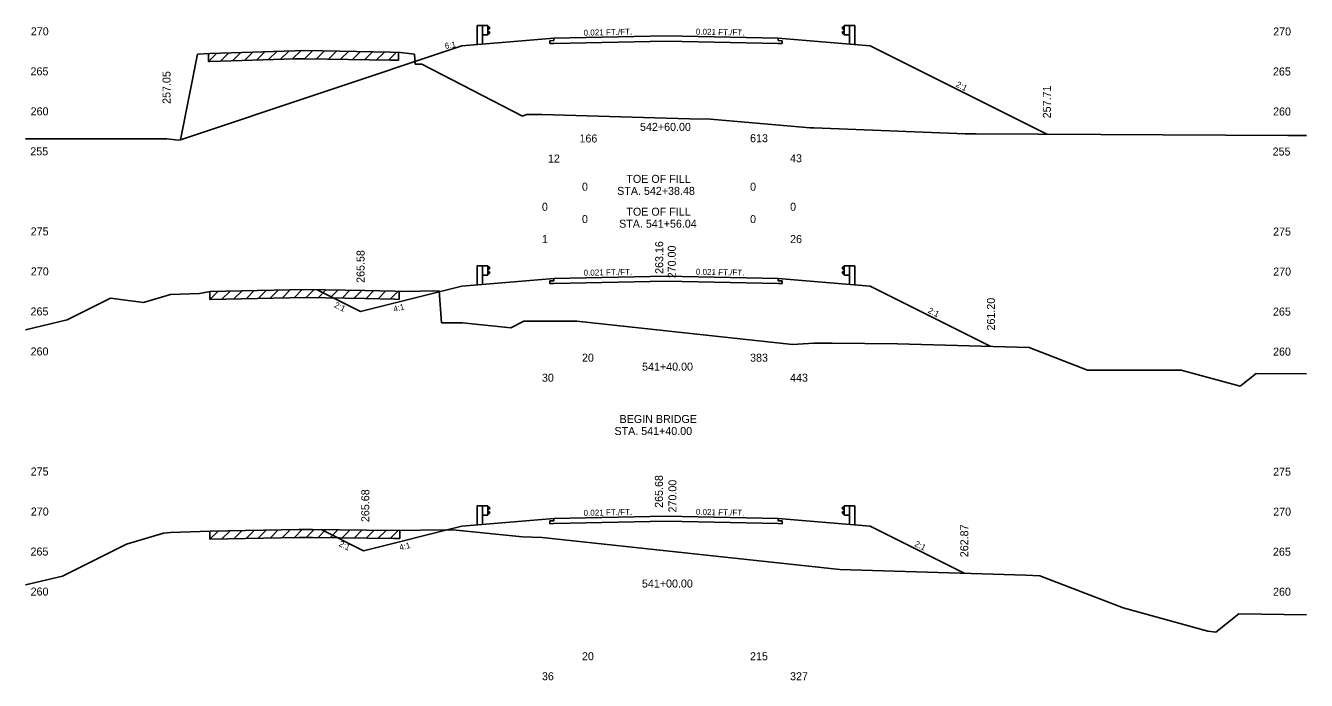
# Model space of a CAD drawing. Extents: x 2967 to 4323, y -3677 to -817.
# Drawn here: x 3555.3 to 3715.3, y -2295.4 to -2213.5 of the extents above; entities that cross this region are included whole.
import ezdxf

# ---------------------------------------------------------------- set-up
doc = ezdxf.new("R2010")
doc.units = 0
for name, color, linetype in [('Level 1', 7, 'Continuous'), ('Level 10', 7, 'Continuous'), ('Level 11', 7, 'Continuous'), ('Level 12', 7, 'Continuous'), ('Level 24', 7, 'Continuous'), ('Level 3', 7, 'Continuous'), ('Level 32', 7, 'Continuous'), ('Level 33', 7, 'Continuous'), ('Level 59', 7, 'Continuous'), ('Level 6', 7, 'Continuous'), ('Level 60', 7, 'Continuous'), ('Level 61', 7, 'Continuous'), ('Level 7', 7, 'Continuous')]:
    doc.layers.add(name, color=color, linetype=linetype)

msp = doc.modelspace()

# ---------------------------------------------------------------- linework, layer by layer
at = {"layer": 'Level 11'}
for p, q in [((3621.35, -2215.43), (3620.85, -2215.44)), ((3620.85, -2215.44), (3620.85, -2215.78)), ((3620.85, -2215.78), (3621.35, -2215.77)), ((3621.35, -2215.13), (3621.35, -2215.43)), ((3649.35, -2215.43), (3649.35, -2215.13)), ((3649.85, -2215.44), (3649.35, -2215.43)), ((3649.35, -2215.77), (3649.85, -2215.78)), ((3649.85, -2215.78), (3649.85, -2215.44)), ((3621.35, -2245.43), (3620.85, -2245.44)), ((3620.85, -2245.44), (3620.85, -2245.78)), ((3620.85, -2245.78), (3621.35, -2245.77)), ((3621.35, -2245.13), (3621.35, -2245.43)), ((3649.35, -2245.43), (3649.35, -2245.13)), ((3649.85, -2245.44), (3649.35, -2245.43)), ((3649.35, -2245.77), (3649.85, -2245.78)), ((3649.85, -2245.78), (3649.85, -2245.44)), ((3621.35, -2275.13), (3621.35, -2275.43)), ((3649.35, -2275.43), (3649.35, -2275.13)), ((3621.35, -2275.43), (3620.85, -2275.44)), ((3620.85, -2275.44), (3620.85, -2275.78)), ((3620.85, -2275.78), (3621.35, -2275.77)), ((3649.85, -2275.44), (3649.35, -2275.43)), ((3649.35, -2275.77), (3649.85, -2275.78)), ((3649.85, -2275.78), (3649.85, -2275.44))]:
    msp.add_line(p, q, dxfattribs=at)
at = {"layer": 'Level 12'}
for p, q in [((3635.35, -2215.48), (3621.35, -2215.77)), ((3649.35, -2215.77), (3635.35, -2215.48)), ((3635.35, -2245.48), (3621.35, -2245.77)), ((3649.35, -2245.77), (3635.35, -2245.48)), ((3635.35, -2275.48), (3621.35, -2275.77)), ((3649.35, -2275.77), (3635.35, -2275.48))]:
    msp.add_line(p, q, dxfattribs=at)
at = {"layer": 'Level 24'}
for p, q in [((3612.41, -2213.55), (3611.75, -2213.55)), ((3611.75, -2213.55), (3611.75, -2215.93)), ((3613.08, -2213.55), (3612.41, -2213.55)), ((3612.41, -2213.55), (3612.41, -2215.88)), ((3613.08, -2214.72), (3613.08, -2213.55)), ((3613.08, -2213.62), (3613.35, -2213.82)), ((3613.35, -2213.87), (3613.08, -2214.07)), ((3613.35, -2214.39), (3613.08, -2214.19)), ((3613.35, -2213.82), (3613.35, -2213.87)), ((3613.35, -2214.44), (3613.35, -2214.39)), ((3657.62, -2213.62), (3657.35, -2213.82)), ((3657.35, -2213.82), (3657.35, -2213.87)), ((3657.35, -2213.87), (3657.62, -2214.07)), ((3657.35, -2214.39), (3657.62, -2214.19)), ((3657.35, -2214.44), (3657.35, -2214.39)), ((3657.62, -2214.72), (3657.62, -2213.55)), ((3657.62, -2213.55), (3658.28, -2213.55)), ((3658.28, -2213.55), (3658.28, -2215.88)), ((3658.28, -2213.55), (3658.95, -2213.55)), ((3658.95, -2213.55), (3658.95, -2215.93)), ((3613.08, -2214.72), (3612.41, -2214.72)), ((3613.08, -2214.64), (3613.35, -2214.44)), ((3657.62, -2214.64), (3657.35, -2214.44)), ((3657.62, -2214.72), (3658.29, -2214.72)), ((3612.41, -2243.55), (3611.75, -2243.55)), ((3611.75, -2243.55), (3611.75, -2245.93)), ((3613.08, -2243.55), (3612.41, -2243.55)), ((3612.41, -2243.55), (3612.41, -2245.88)), ((3613.08, -2244.72), (3612.41, -2244.72)), ((3613.08, -2244.72), (3613.08, -2243.55)), ((3613.08, -2243.62), (3613.35, -2243.82)), ((3613.35, -2243.87), (3613.08, -2244.07)), ((3613.35, -2244.39), (3613.08, -2244.19)), ((3613.08, -2244.64), (3613.35, -2244.44)), ((3613.35, -2243.82), (3613.35, -2243.87)), ((3613.35, -2244.44), (3613.35, -2244.39)), ((3657.62, -2243.62), (3657.35, -2243.82)), ((3657.35, -2243.82), (3657.35, -2243.87)), ((3657.35, -2243.87), (3657.62, -2244.07)), ((3657.35, -2244.39), (3657.62, -2244.19)), ((3657.35, -2244.44), (3657.35, -2244.39)), ((3657.62, -2244.64), (3657.35, -2244.44)), ((3657.62, -2244.72), (3657.62, -2243.55)), ((3657.62, -2243.55), (3658.28, -2243.55)), ((3657.62, -2244.72), (3658.29, -2244.72)), ((3658.28, -2243.55), (3658.28, -2245.88)), ((3658.28, -2243.55), (3658.95, -2243.55)), ((3658.95, -2243.55), (3658.95, -2245.93)), ((3612.41, -2273.55), (3611.75, -2273.55)), ((3611.75, -2273.55), (3611.75, -2275.93)), ((3613.08, -2273.55), (3612.41, -2273.55)), ((3612.41, -2273.55), (3612.41, -2275.88)), ((3613.08, -2274.72), (3613.08, -2273.55)), ((3657.62, -2274.72), (3657.62, -2273.55)), ((3657.62, -2273.55), (3658.28, -2273.55)), ((3658.28, -2273.55), (3658.28, -2275.88)), ((3658.28, -2273.55), (3658.95, -2273.55)), ((3658.95, -2273.55), (3658.95, -2275.93)), ((3613.08, -2274.72), (3612.41, -2274.72)), ((3613.08, -2273.62), (3613.35, -2273.82)), ((3613.35, -2273.87), (3613.08, -2274.07)), ((3613.35, -2274.39), (3613.08, -2274.19)), ((3613.08, -2274.64), (3613.35, -2274.44)), ((3613.35, -2273.82), (3613.35, -2273.87)), ((3613.35, -2274.44), (3613.35, -2274.39)), ((3657.62, -2273.62), (3657.35, -2273.82)), ((3657.35, -2273.82), (3657.35, -2273.87)), ((3657.35, -2273.87), (3657.62, -2274.07)), ((3657.35, -2274.39), (3657.62, -2274.19)), ((3657.35, -2274.44), (3657.35, -2274.39)), ((3657.62, -2274.64), (3657.35, -2274.44)), ((3657.62, -2274.72), (3658.29, -2274.72))]:
    msp.add_line(p, q, dxfattribs=at)
at = {"layer": 'Level 59'}
for p, q in [((3621.35, -2215.13), (3635.35, -2214.84)), ((3635.35, -2214.84), (3649.35, -2215.13)), ((3621.35, -2245.13), (3635.35, -2244.84)), ((3635.35, -2244.84), (3649.35, -2245.13)), ((3621.35, -2275.13), (3635.35, -2274.84)), ((3635.35, -2274.84), (3649.35, -2275.13))]:
    msp.add_line(p, q, dxfattribs=at)
at = {"layer": 'Level 6'}
for p, q in [((3609.85, -2216.09), (3621.35, -2215.13)), ((3649.35, -2215.13), (3657.35, -2215.8)), ((3657.35, -2215.8), (3660.85, -2216.09)), ((3613.35, -2245.8), (3621.35, -2245.13)), ((3649.35, -2245.13), (3657.35, -2245.8)), ((3657.35, -2245.8), (3660.85, -2246.09)), ((3609.85, -2276.09), (3621.35, -2275.13)), ((3649.35, -2275.13), (3657.35, -2275.8)), ((3657.35, -2275.8), (3660.85, -2276.09))]:
    msp.add_line(p, q, dxfattribs=at)
at = {"layer": 'Level 60'}
for p, q in [((3574.68, -2227.8), (3576.84, -2217.13)), ((3576.84, -2217.13), (3578.36, -2217.02)), ((3578.36, -2217.02), (3589, -2216.7)), ((3589, -2216.7), (3590.34, -2216.68)), ((3590.34, -2216.68), (3600.95, -2216.86)), ((3600.95, -2216.86), (3602.18, -2216.89)), ((3602.18, -2216.89), (3603.92, -2217.11)), ((3603.92, -2217.11), (3604.03, -2218.38)), ((3604.03, -2218.38), (3604.86, -2218.38)), ((3604.86, -2218.38), (3617.44, -2224.87)), ((3617.44, -2224.87), (3617.91, -2224.64)), ((3617.91, -2224.64), (3619.85, -2224.64)), ((3619.85, -2224.64), (3635.35, -2225.12)), ((3635.35, -2225.12), (3639.75, -2225.25)), ((3639.75, -2225.25), (3640.39, -2225.21)), ((3640.39, -2225.21), (3653.34, -2226.32)), ((3653.34, -2226.32), (3653.82, -2226.32)), ((3653.82, -2226.32), (3672.73, -2227.07)), ((3672.73, -2227.07), (3674.08, -2227.09)), ((3674.08, -2227.09), (3713.02, -2227.3)), ((3555.35, -2227.69), (3572.97, -2227.69)), ((3572.97, -2227.69), (3574.43, -2227.88)), ((3574.43, -2227.88), (3574.68, -2227.8)), ((3713.02, -2227.3), (3713.78, -2227.3)), ((3713.78, -2227.3), (3715.35, -2227.28)), ((3560.55, -2250.33), (3565.95, -2247.62)), ((3565.95, -2247.62), (3570.09, -2248.13)), ((3570.09, -2248.13), (3573.45, -2247.15)), ((3573.45, -2247.15), (3577.05, -2247.03)), ((3577.05, -2247.03), (3578.4, -2246.75)), ((3578.4, -2246.75), (3582.33, -2246.68)), ((3582.33, -2246.68), (3590.37, -2246.53)), ((3590.37, -2246.53), (3597.71, -2246.64)), ((3597.71, -2246.64), (3601.46, -2246.72)), ((3601.46, -2246.72), (3602.2, -2246.77)), ((3602.2, -2246.77), (3606.99, -2246.7)), ((3606.99, -2246.7), (3607.32, -2250.7)), ((3555.35, -2251.57), (3560.55, -2250.33)), ((3607.32, -2250.7), (3609.94, -2250.7)), ((3609.94, -2250.7), (3615.95, -2251.3)), ((3615.95, -2251.3), (3617.58, -2250.48)), ((3617.58, -2250.48), (3624.21, -2250.48)), ((3624.21, -2250.48), (3635.35, -2251.69)), ((3635.35, -2251.69), (3651.17, -2253.4)), ((3651.17, -2253.4), (3653.81, -2253.24)), ((3653.81, -2253.24), (3656.11, -2253.23)), ((3656.11, -2253.23), (3664.25, -2253.29)), ((3664.25, -2253.29), (3680.72, -2253.78)), ((3680.72, -2253.78), (3687.99, -2256.58)), ((3687.99, -2256.58), (3699.72, -2256.61)), ((3699.72, -2256.61), (3707.07, -2258.6)), ((3707.07, -2258.6), (3709.06, -2257.01)), ((3709.06, -2257.01), (3715.35, -2257.07)), ((3573.44, -2276.88), (3578.4, -2276.72)), ((3578.4, -2276.72), (3589.49, -2276.52)), ((3589.49, -2276.52), (3590.36, -2276.5)), ((3590.36, -2276.5), (3591.19, -2276.5)), ((3591.19, -2276.5), (3601.33, -2276.64)), ((3601.33, -2276.64), (3607.95, -2276.55)), ((3607.95, -2276.55), (3609.13, -2276.57)), ((3609.13, -2276.57), (3617.42, -2277.41)), ((3567.35, -2278.64), (3567.95, -2278.34)), ((3567.95, -2278.34), (3572.58, -2276.98)), ((3572.58, -2276.98), (3572.99, -2276.91)), ((3572.99, -2276.91), (3573.44, -2276.88)), ((3617.42, -2277.41), (3619.86, -2277.49)), ((3619.86, -2277.49), (3635.35, -2279.16)), ((3559.95, -2282.34), (3567.35, -2278.64)), ((3635.35, -2279.16), (3657.08, -2281.51)), ((3657.08, -2281.51), (3680.28, -2282.2)), ((3555.35, -2283.42), (3559.95, -2282.34)), ((3680.28, -2282.2), (3682.03, -2282.29)), ((3682.03, -2282.29), (3692.46, -2286.3)), ((3692.46, -2286.3), (3703.02, -2289.21)), ((3704.03, -2289.34), (3706.89, -2287.06)), ((3706.89, -2287.06), (3715.35, -2287.16)), ((3703.02, -2289.21), (3704.03, -2289.34))]:
    msp.add_line(p, q, dxfattribs=at)
at = {"layer": 'Level 61'}
for p, q in [((3579.23, -2217), (3578.19, -2218.04)), ((3578.19, -2217.04), (3578.19, -2218.04)), ((3580.72, -2216.95), (3579.69, -2217.98)), ((3582.22, -2216.91), (3581.19, -2217.94)), ((3583.72, -2216.86), (3582.69, -2217.89)), ((3585.22, -2216.82), (3584.19, -2217.85)), ((3586.72, -2216.77), (3585.69, -2217.8)), ((3588.22, -2216.73), (3587.19, -2217.76)), ((3589.71, -2216.69), (3588.69, -2217.71)), ((3591.18, -2216.7), (3590.19, -2217.68)), ((3592.68, -2216.72), (3591.69, -2217.7)), ((3594.18, -2216.75), (3593.19, -2217.73)), ((3595.68, -2216.77), (3594.69, -2217.76)), ((3597.18, -2216.8), (3596.19, -2217.78)), ((3598.68, -2216.82), (3597.69, -2217.81)), ((3600.18, -2216.85), (3599.19, -2217.83)), ((3601.67, -2216.88), (3600.69, -2217.86)), ((3601.92, -2217.88), (3601.92, -2216.88)), ((3578.19, -2218.04), (3578.36, -2218.02)), ((3578.36, -2218.02), (3589, -2217.7)), ((3589, -2217.7), (3590.34, -2217.68)), ((3590.34, -2217.68), (3600.95, -2217.86)), ((3600.95, -2217.86), (3601.92, -2217.88)), ((3579.4, -2246.73), (3578.38, -2247.75)), ((3578.38, -2246.75), (3578.38, -2247.75)), ((3578.38, -2247.75), (3578.4, -2247.75)), ((3578.4, -2247.75), (3582.33, -2247.68)), ((3580.89, -2246.71), (3579.88, -2247.72)), ((3582.39, -2246.68), (3581.38, -2247.7)), ((3582.33, -2247.68), (3590.37, -2247.53)), ((3583.89, -2246.65), (3582.88, -2247.67)), ((3585.39, -2246.63), (3584.38, -2247.64)), ((3586.9, -2246.6), (3585.88, -2247.62)), ((3588.4, -2246.57), (3587.38, -2247.59)), ((3589.9, -2246.54), (3588.88, -2247.56)), ((3590.37, -2247.53), (3597.71, -2247.64)), ((3591.36, -2246.55), (3590.38, -2247.53)), ((3592.86, -2246.57), (3591.88, -2247.56)), ((3594.36, -2246.59), (3593.38, -2247.58)), ((3595.86, -2246.61), (3594.88, -2247.6)), ((3597.36, -2246.63), (3596.38, -2247.62)), ((3597.71, -2247.64), (3601.46, -2247.72)), ((3598.85, -2246.66), (3597.88, -2247.64)), ((3600.35, -2246.7), (3599.38, -2247.67)), ((3601.84, -2246.75), (3600.88, -2247.71)), ((3601.46, -2247.72), (3602.02, -2247.76)), ((3602.02, -2247.76), (3602.02, -2246.76)), ((3579.4, -2276.7), (3578.38, -2277.72)), ((3578.38, -2276.72), (3578.38, -2277.72)), ((3580.9, -2276.67), (3579.88, -2277.69)), ((3582.4, -2276.65), (3581.38, -2277.66)), ((3583.9, -2276.62), (3582.88, -2277.64)), ((3585.4, -2276.59), (3584.38, -2277.61)), ((3586.9, -2276.56), (3585.88, -2277.58)), ((3588.4, -2276.54), (3587.38, -2277.55)), ((3589.9, -2276.51), (3588.88, -2277.53)), ((3591.38, -2276.5), (3590.38, -2277.5)), ((3592.87, -2276.52), (3591.88, -2277.51)), ((3594.37, -2276.55), (3593.38, -2277.53)), ((3595.87, -2276.57), (3594.88, -2277.55)), ((3597.37, -2276.59), (3596.38, -2277.57)), ((3598.87, -2276.61), (3597.88, -2277.59)), ((3600.37, -2276.63), (3599.38, -2277.61)), ((3601.89, -2276.63), (3600.88, -2277.63)), ((3602.08, -2277.63), (3602.08, -2276.63)), ((3578.38, -2277.72), (3578.4, -2277.72)), ((3578.4, -2277.72), (3589.49, -2277.52)), ((3589.49, -2277.52), (3590.36, -2277.5)), ((3590.36, -2277.5), (3591.19, -2277.5)), ((3591.19, -2277.5), (3601.33, -2277.64)), ((3601.33, -2277.64), (3602.08, -2277.63))]:
    msp.add_line(p, q, dxfattribs=at)
at = {"layer": 'Level 7'}
for p, q in [((3609.85, -2216.09), (3574.68, -2227.8)), ((3660.85, -2216.09), (3682.93, -2227.13)), ((3609.85, -2246.09), (3597.18, -2249.26)), ((3609.85, -2246.09), (3613.35, -2245.8)), ((3660.85, -2246.09), (3675.94, -2253.64)), ((3597.18, -2249.26), (3591.77, -2246.55)), ((3597.55, -2279.17), (3592.25, -2276.52)), ((3609.85, -2276.09), (3597.55, -2279.17)), ((3660.85, -2276.09), (3672.61, -2281.97))]:
    msp.add_line(p, q, dxfattribs=at)

# ---------------------------------------------------------------- texts
at = {"layer": 'Level 1'}
for s, p in [('166', (3624.54, -2228.15)), ('613', (3645.85, -2228.12)), ('12', (3620.6, -2230.66)), ('43', (3650.85, -2230.62)), ('0', (3624.85, -2234.18)), ('TOE OF FILL', (3630.4, -2233.2)), ('0', (3645.85, -2234.18)), ('STA. 542+38.48', (3629.25, -2234.7)), ('0', (3619.85, -2236.68)), ('TOE OF FILL', (3630.4, -2237.3)), ('0', (3650.85, -2236.68)), ('0', (3624.85, -2238.22)), ('STA. 541+56.04', (3629.49, -2238.8)), ('0', (3645.85, -2238.22)), ('1', (3619.85, -2240.72)), ('26', (3650.85, -2240.72)), ('20', (3624.85, -2255.54)), ('383', (3645.85, -2255.54)), ('30', (3619.85, -2258.04)), ('443', (3650.85, -2258.04)), ('BEGIN BRIDGE', (3629.55, -2263.2)), ('STA. 541+40.00', (3628.91, -2264.7)), ('20', (3624.85, -2292.84)), ('215', (3645.85, -2292.84)), ('36', (3619.85, -2295.34)), ('327', (3650.85, -2295.34))]:
    msp.add_text(s, height=1, dxfattribs=at).set_placement(p)
at = {"layer": 'Level 10'}
for s, p in [('542+60.00', (3632.1, -2226.7)), ('541+40.00', (3632.36, -2256.66)), ('541+00.00', (3632.34, -2283.76))]:
    msp.add_text(s, height=1, dxfattribs=at).set_placement(p)
for s, p in [('263.16', (3635, -2244.57)), ('265.68', (3634.96, -2273.8))]:
    msp.add_text(s, height=1, rotation=90, dxfattribs=at).set_placement(p)
at = {"layer": 'Level 3'}
for s, p in [(' 270', (3555.63, -2214.76)), (' 270', (3710.83, -2214.78)), (' 265', (3555.59, -2219.76)), (' 265', (3710.8, -2219.78)), (' 260', (3555.6, -2224.76)), (' 260', (3710.81, -2224.78)), (' 255', (3555.56, -2229.76)), (' 255', (3710.76, -2229.78)), (' 275', (3555.61, -2239.76)), (' 275', (3710.82, -2239.78)), (' 270', (3555.63, -2244.76)), (' 270', (3710.83, -2244.78)), (' 265', (3555.59, -2249.76)), (' 265', (3710.8, -2249.78)), (' 260', (3555.6, -2254.76)), (' 260', (3710.81, -2254.78)), (' 275', (3555.61, -2269.76)), (' 275', (3710.82, -2269.78)), (' 270', (3555.63, -2274.76)), (' 270', (3710.83, -2274.78)), (' 265', (3555.59, -2279.76)), (' 265', (3710.8, -2279.78)), (' 260', (3555.6, -2284.76)), (' 260', (3710.81, -2284.78))]:
    msp.add_text(s, height=1, dxfattribs=at).set_placement(p)
at = {"layer": 'Level 32'}
for s, rotation, p in [('0.021 FT./FT.', 1.1916, (3625.06, -2214.81)), ('0.021 FT./FT.', 358.8084, (3639.07, -2214.67)), ('6:1', 9.4623, (3607.78, -2216.47)), ('2:1', 333.435, (3671.5, -2221.14)), ('0.021 FT./FT.', 1.1916, (3625.06, -2244.81)), ('0.021 FT./FT.', 1.1916, (3625.06, -2244.81)), ('0.021 FT./FT.', 358.8084, (3639.07, -2244.67)), ('0.021 FT./FT.', 358.8084, (3639.07, -2244.67)), ('2:1', 333.435, (3593.82, -2248.7)), ('4:1', 14.0362, (3601.38, -2249.34)), ('2:1', 333.435, (3668, -2249.39)), ('0.021 FT./FT.', 1.1916, (3625.06, -2274.81)), ('0.021 FT./FT.', 358.8084, (3639.07, -2274.67)), ('2:1', 333.435, (3594.41, -2278.54)), ('4:1', 14.0362, (3602.13, -2279.14)), ('2:1', 333.435, (3666.33, -2278.55))]:
    msp.add_text(s, height=0.75, rotation=rotation, dxfattribs=at).set_placement(p)
at = {"layer": 'Level 33'}
for s, p in [('257.05', (3573.45, -2223.33)), ('257.71', (3683.43, -2225.13)), ('265.58', (3597.69, -2245.69)), ('261.20', (3676.44, -2251.64)), ('265.68', (3598.28, -2275.58)), ('262.87', (3673.11, -2279.97))]:
    msp.add_text(s, height=1, rotation=90, dxfattribs=at).set_placement(p)
at = {"layer": 'Level 59'}
for p in [(3636.57, -2245.49), (3636.65, -2274.75)]:
    msp.add_text(' 270.00', height=1, rotation=90, dxfattribs=at).set_placement(p)

doc.saveas('drawing.dxf')
